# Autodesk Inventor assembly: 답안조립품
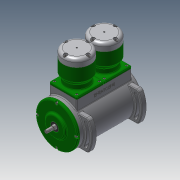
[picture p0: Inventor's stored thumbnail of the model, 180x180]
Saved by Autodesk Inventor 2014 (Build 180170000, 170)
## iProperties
Created: 2017-08
Part Number: 답안조립품
Document SubType Name: Assembly
Designer: user
Mass: 7428.06 g
Surface Area: 5102.67 cm^2
Volume: 2063.03 cm^3
Density: 3.60056 g/cm^3
Author: user
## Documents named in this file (16)
- C:\Users\user\Desktop\370808V1004\답안조립품.iam
- C:\Users\user\Desktop\370808V1004\본체.ipt
- C:\Users\user\Desktop\370808V1004\너트 M4.ipt
- C:\Users\user\Desktop\370808V1004\베어링 12 x 28 x 8.ipt
- C:\Users\user\Desktop\370808V1004\볼트 M4 x 8.ipt
- C:\Users\user\Desktop\370808V1004\볼트 M5 x 20.ipt
- C:\Users\user\Desktop\370808V1004\실린더.ipt
- C:\Users\user\Desktop\370808V1004\실린더헤드.ipt
- C:\Users\user\Desktop\370808V1004\앞커버.ipt
- C:\Users\user\Desktop\370808V1004\오일 실 12 25 7.ipt
- C:\Users\user\Desktop\370808V1004\육각 머리 볼트 M4 x 16.ipt
- C:\Users\user\Desktop\370808V1004\커넥팅로드 엔드.ipt
- C:\Users\user\Desktop\370808V1004\커넥팅로드.ipt
- C:\Users\user\Desktop\370808V1004\크랭크축.ipt
- C:\Users\user\Desktop\370808V1004\피스톤.ipt
- C:\Users\user\Desktop\370808V1004\피스톤핀.ipt
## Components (4 placed, 2 different names)
1. 피스톤:1
2. 피스톤핀:1
3. 피스톤:2
4. 피스톤핀:2
## Named parameters: d20_d19 = 0, d29_d23 = 0, d30_d24 = 0, d31_d25 = 0, d32_d26 = 0, d33_d10 = 0, d34_d11 = 0, d35_d12 = 0, d36_d13 = 0, d37_d14 = 0, d38_d15 = 0, d39_d16 = 0, d40_d17 = 0, d41_d18 = 0, d42_d19 = 0, d43_d20_d19 = 0, d44_d21 = 0, d45_d22 = 0, d46_d8 = 0, d47_d9 = 0
